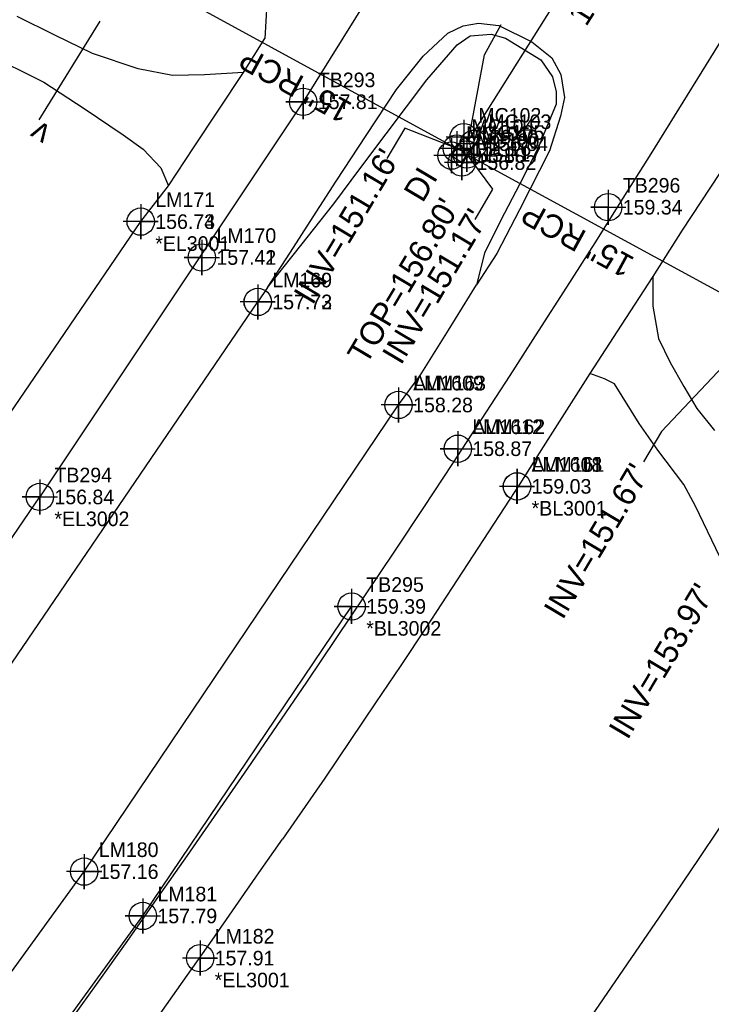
# Model space of a CAD drawing. Extents: x 2262665 to 2270527, y 505476 to 514960.
# Drawn here: x 2265771.7 to 2265890.1, y 508685.4 to 508854 of the extents above; entities that cross this region are included whole.
import ezdxf

# ---------------------------------------------------------------- set-up
doc = ezdxf.new("R2010")
doc.units = 0
for name, color, linetype in [('Exist Horizontal Alignment', 7, 'Continuous'), ('Exist Right of Way Control of Access Line', 7, 'Continuous'), ('Exist Roads EOP', 7, 'Continuous'), ('Exist Roads EOP Cogo Comment', 7, 'Continuous'), ('Exist Roads EOP Cogo Elevation', 7, 'Continuous'), ('Exist Roads EOP Cogo Number', 7, 'Continuous'), ('Exist Roads EOP Cogo Point CELL', 7, 'Continuous'), ('Exist Roads EOP Other', 7, 'Continuous'), ('Exist Roads EOT', 7, 'Continuous'), ('Exist Roads EOT Cogo Comment', 7, 'Continuous'), ('Exist Roads EOT Cogo Elevation', 7, 'Continuous'), ('Exist Roads EOT Cogo Number', 7, 'Continuous'), ('Exist Roads EOT Cogo Point CELL', 7, 'Continuous'), ('Exist Roads Soil', 7, 'Continuous'), ('Exist Structure Minor Culvert Topo', 7, 'Continuous'), ('Exist Structure Minor Culvert Topo Terminator', 7, 'Continuous'), ('Exist Structure Minor Drop Inlet', 7, 'Continuous'), ('Exist Structure Minor Drop Inlet Cogo Elevation', 7, 'Continuous'), ('Exist Structure Minor Drop Inlet Cogo Number', 7, 'Continuous'), ('Exist Structure Minor Drop Inlet Cogo Point CELL', 7, 'Continuous'), ('Exist Structure Minor Drop Inlet Text', 7, 'Continuous'), ('Exist Structure Minor Drop Inlet Top Elevation', 7, 'Continuous'), ('Exist Structure Minor Pipes RCP 15 Inch', 7, 'Continuous'), ('Exist Structure Minor Pipes RCP 15 Inch Cogo Elevation', 7, 'Continuous'), ('Exist Structure Minor Pipes RCP 15 Inch Cogo Number', 7, 'Continuous'), ('Exist Structure Minor Pipes RCP 15 Inch Cogo Point CELL', 7, 'Continuous'), ('Exist Structure Minor Pipes RCP 15 Inch Invert', 7, 'Continuous'), ('Exist Structure Minor Pipes RCP 15 Inch Leader', 7, 'Continuous'), ('Exist Structure Minor Pipes RCP 15 Inch Text', 7, 'Continuous')]:
    doc.layers.add(name, color=color, linetype=linetype)

msp = doc.modelspace()

# ---------------------------------------------------------------- linework, layer by layer
at = {"layer": 'Exist Horizontal Alignment'}
msp.add_arc((2263436.25, 510359.19), 2882, 309.60499, 355.6461, dxfattribs=at)
at = {"layer": 'Exist Right of Way Control of Access Line'}
for radius, end in [(2754.56, 355.6461), (2954.56, 339.73535)]:
    msp.add_arc((2263436.25, 510359.19), radius, 309.60499, end, dxfattribs=at)
at = {"layer": 'Exist Roads EOP'}
for points in [[(2265910.12, 508858.21), (2265905.83, 508851.47), (2265901.54, 508844.73), (2265897.25, 508838), (2265891.48, 508827.67), (2265885.09, 508817.97)], [(2265792.39, 508819.43), (2265797.17, 508825.59), (2265801.44, 508832.06), (2265805.72, 508838.52), (2265809.99, 508844.99), (2265813.65, 508850.79)], [(2265814.12, 508808.16), (2265819.79, 508815.33), (2265825.46, 508822.49), (2265829.92, 508828.48), (2265834.38, 508834.46), (2265841.35, 508843.7), (2265846.57, 508849.72), (2265848.81, 508851.24), (2265852.38, 508851.52), (2265854.86, 508850.83), (2265860.89, 508847.12), (2265862.9, 508844.22), (2265863.52, 508841.67), (2265863.48, 508839.57), (2265860.33, 508831.82), (2265857.2, 508825.77), (2265854.06, 508819.71), (2265851.22, 508814.06), (2265849.86, 508808.6)], [(2265756.07, 508766.2), (2265792.39, 508819.43)], [(2265885.09, 508817.97), (2265880.03, 508810.04), (2265874.65, 508801.73), (2265869.26, 508793.42), (2265865.26, 508787.14), (2265861.27, 508780.85), (2265857.27, 508774.56), (2265851.92, 508766.34), (2265846.57, 508758.12), (2265841.22, 508749.89), (2265836.89, 508743.46), (2265832.57, 508737.02), (2265828.24, 508730.59), (2265823.91, 508724.16), (2265816.65, 508713.72)], [(2265814.12, 508808.16), (2265812.43, 508805.68)], [(2265836.53, 508788.04), (2265840.23, 508793.07), (2265845.05, 508800.83), (2265849.86, 508808.6)], [(2264604.13, 507673.17), (2264652.18, 507710.12), (2264729.46, 507770.12), (2264804.34, 507827.5), (2264878.61, 507884.49), (2264953.4, 507941.83), (2265025.73, 507997.77), (2265100.61, 508055.34), (2265175.62, 508113.68), (2265249.21, 508173.29), (2265321.97, 508235.58), (2265396.59, 508304.14), (2265463.32, 508369.68), (2265525.52, 508435.63), (2265587.08, 508505.56), (2265646.09, 508576.73), (2265702.44, 508648.91), (2265758.48, 508726.47), (2265812.43, 508805.68)], [(2264622.96, 507650.09), (2264669.69, 507686.11), (2264747.6, 507746.03), (2264823.02, 507803.99), (2264895.49, 507859.73), (2264970.56, 507917.69), (2265042.91, 507973.75), (2265117.63, 508031.26), (2265192.77, 508089.56), (2265267.51, 508149.88), (2265340.79, 508212.44), (2265416.18, 508281.7), (2265483.07, 508347.24), (2265547.56, 508415.53), (2265609.81, 508485.51), (2265669.26, 508556.91), (2265726.09, 508630), (2265782.72, 508708.15), (2265836.53, 508788.04)], [(2265771.46, 508649.69), (2265775.99, 508656.02), (2265781.29, 508663.45), (2265786.58, 508670.88), (2265791.88, 508678.31), (2265796.12, 508684.35), (2265800.36, 508690.38), (2265804.6, 508696.42), (2265808.62, 508702.19), (2265812.63, 508707.96), (2265816.65, 508713.72)]]:
    msp.add_lwpolyline(points, dxfattribs=at)
at = {"layer": 'Exist Roads EOP Cogo Point CELL'}
for points in [[(2265792.39, 508822.43), (2265792.39, 508816.43), (2265792.39, 508819.43), (2265795.39, 508819.43), (2265789.39, 508819.43)], [(2265792.39, 508822.43), (2265792.39, 508816.43), (2265792.39, 508819.43), (2265795.39, 508819.43), (2265789.39, 508819.43)], [(2265812.42, 508808.68), (2265812.42, 508802.68), (2265812.42, 508805.68), (2265815.42, 508805.68), (2265809.42, 508805.68)], [(2265812.43, 508808.68), (2265812.43, 508802.68), (2265812.43, 508805.68), (2265815.43, 508805.68), (2265809.43, 508805.68)], [(2265836.53, 508791.04), (2265836.53, 508785.04), (2265836.53, 508788.04), (2265839.53, 508788.04), (2265833.53, 508788.04)], [(2265836.53, 508791.04), (2265836.53, 508785.04), (2265836.53, 508788.04), (2265839.53, 508788.04), (2265833.53, 508788.04)], [(2265856.8, 508777.11), (2265856.8, 508771.11), (2265856.8, 508774.11), (2265859.8, 508774.11), (2265853.8, 508774.11)], [(2265856.81, 508777.11), (2265856.81, 508771.11), (2265856.81, 508774.11), (2265859.81, 508774.11), (2265853.81, 508774.11)], [(2265856.81, 508777.11), (2265856.81, 508771.11), (2265856.81, 508774.11), (2265859.81, 508774.11), (2265853.81, 508774.11)], [(2265782.71, 508711.15), (2265782.71, 508705.15), (2265782.71, 508708.15), (2265785.71, 508708.15), (2265779.71, 508708.15)], [(2265782.72, 508711.15), (2265782.72, 508705.15), (2265782.72, 508708.15), (2265785.72, 508708.15), (2265779.72, 508708.15)], [(2265802.56, 508696.34), (2265802.56, 508690.34), (2265802.56, 508693.34), (2265805.56, 508693.34), (2265799.56, 508693.34)], [(2265802.56, 508696.34), (2265802.56, 508690.34), (2265802.56, 508693.34), (2265805.56, 508693.34), (2265799.56, 508693.34)]]:
    msp.add_lwpolyline(points, dxfattribs=at)
for centre in [(2265792.39, 508819.43), (2265792.39, 508819.43), (2265812.43, 508805.68), (2265812.42, 508805.68), (2265836.53, 508788.04), (2265836.53, 508788.04), (2265856.81, 508774.11), (2265856.81, 508774.11), (2265856.8, 508774.11), (2265782.71, 508708.15), (2265782.72, 508708.15), (2265802.56, 508693.34), (2265802.56, 508693.34)]:
    msp.add_circle(centre, 2.34, dxfattribs=at)
at = {"layer": 'Exist Roads EOP Other'}
msp.add_lwpolyline([(2265813.96, 508856.74), (2265813.65, 508850.79)], dxfattribs=at)
at = {"layer": 'Exist Roads EOT'}
for points in [[(2265966, 509095.96), (2265942.58, 509050.45), (2265904.19, 508979.11), (2265863.41, 508909.33), (2265820.21, 508839.95), (2265775.13, 508772.3)], [(2265814.12, 508808.16), (2265818.03, 508814.22), (2265821.94, 508820.28), (2265825.85, 508826.34), (2265831.01, 508834.18), (2265836.17, 508842.03), (2265840.75, 508847.78), (2265844.95, 508851.68), (2265847.58, 508852.94), (2265850.19, 508853.44), (2265853.69, 508853.02), (2265859.36, 508850.21), (2265862.75, 508847.46), (2265864.32, 508844.61), (2265864.91, 508840.71), (2265864.25, 508837.47), (2265862.39, 508831.53), (2265857.21, 508821.44), (2265853.34, 508814), (2265849.86, 508808.6)], [(2264355.6, 507490.59), (2264438.39, 507557.92), (2264515.74, 507619.63), (2264596.53, 507682.98), (2264644.8, 507719.95), (2264722.22, 507780.13), (2264797.31, 507837.32), (2264871.27, 507893.95), (2264945.98, 507951.46), (2265019.16, 508007.99), (2265093.77, 508065.17), (2265168.17, 508123.63), (2265241.66, 508182.89), (2265313.79, 508245.24), (2265388.67, 508313.15), (2265454.9, 508378.68), (2265516.64, 508444.01), (2265578.28, 508513.6), (2265637.19, 508584.7), (2265692.99, 508656.91), (2265748.78, 508733.7), (2265775.13, 508772.3)], [(2264387.25, 507447.54), (2264469.24, 507514.31), (2264548.37, 507577.38), (2264630.86, 507640.65), (2264676.76, 507676.3), (2264754.66, 507736.06), (2264830.22, 507794.41), (2264902.47, 507849.79), (2264977.44, 507907.47), (2265049.71, 507963.66), (2265125.01, 508021.39), (2265200.16, 508080.1), (2265274.69, 508140.15), (2265348.74, 508203.05), (2265424.49, 508272.43), (2265491.61, 508338.47), (2265557.1, 508407.36), (2265618.9, 508477.1), (2265678.7, 508548.94), (2265735.91, 508622.32), (2265792.76, 508700.56), (2265828.5, 508753.55)]]:
    msp.add_lwpolyline(points, dxfattribs=at)
at = {"layer": 'Exist Roads EOT Cogo Point CELL'}
for points in [[(2265820.21, 508842.95), (2265820.21, 508836.95), (2265820.21, 508839.95), (2265817.21, 508839.95), (2265823.21, 508839.95)], [(2265872.41, 508824.9), (2265872.41, 508818.9), (2265872.41, 508821.9), (2265869.41, 508821.9), (2265875.41, 508821.9)], [(2265802.86, 508816.3), (2265802.86, 508810.3), (2265802.86, 508813.3), (2265799.86, 508813.3), (2265805.86, 508813.3)], [(2265802.86, 508816.29), (2265802.86, 508810.29), (2265802.86, 508813.29), (2265799.86, 508813.29), (2265805.86, 508813.29)], [(2265846.66, 508783.56), (2265846.66, 508777.56), (2265846.66, 508780.56), (2265843.66, 508780.56), (2265849.66, 508780.56)], [(2265846.66, 508783.56), (2265846.66, 508777.56), (2265846.66, 508780.56), (2265843.66, 508780.56), (2265849.66, 508780.56)], [(2265775.13, 508775.3), (2265775.13, 508769.3), (2265775.13, 508772.3), (2265772.13, 508772.3), (2265778.13, 508772.3)], [(2265828.5, 508756.55), (2265828.5, 508750.55), (2265828.5, 508753.55), (2265825.5, 508753.55), (2265831.5, 508753.55)], [(2265792.75, 508703.56), (2265792.75, 508697.56), (2265792.75, 508700.56), (2265789.75, 508700.56), (2265795.75, 508700.56)], [(2265792.76, 508703.56), (2265792.76, 508697.56), (2265792.76, 508700.56), (2265789.76, 508700.56), (2265795.76, 508700.56)]]:
    msp.add_lwpolyline(points, dxfattribs=at)
for centre in [(2265820.21, 508839.95), (2265872.41, 508821.9), (2265802.86, 508813.29), (2265802.86, 508813.3), (2265846.66, 508780.56), (2265846.66, 508780.56), (2265775.13, 508772.3), (2265828.5, 508753.55), (2265792.75, 508700.56), (2265792.76, 508700.56)]:
    msp.add_circle(centre, 2.34, dxfattribs=at)
at = {"layer": 'Exist Roads Soil'}
for points in [[(2265749.14, 508856.82), (2265755.11, 508853.6), (2265765.64, 508848.34), (2265775.81, 508843.33), (2265782.69, 508838.81), (2265789.38, 508834.27), (2265792.84, 508831.82), (2265795.84, 508828.66), (2265797.17, 508825.59)], [(2265809.99, 508844.99), (2265803.32, 508844.59), (2265797.85, 508844.44), (2265791.95, 508845.58), (2265784.15, 508848.21), (2265777.68, 508851.37), (2265771.22, 508854.53)], [(2265880.03, 508810.04), (2265880.04, 508804.96), (2265881.01, 508799.43), (2265883.04, 508795.33), (2265885.37, 508791.19), (2265887.56, 508787.45), (2265890.6, 508783.65)], [(2265891.5, 508762.02), (2265887.34, 508770.72), (2265885.38, 508774.44), (2265880.91, 508780.32), (2265877.69, 508784.89), (2265873.5, 508791.64), (2265871.79, 508792.54), (2265869.26, 508793.42)]]:
    msp.add_lwpolyline(points, dxfattribs=at)
at = {"layer": 'Exist Structure Minor Culvert Topo'}
msp.add_line((2265775.02, 508836.84), (2265785.47, 508853.73), dxfattribs=at)
at = {"layer": 'Exist Structure Minor Drop Inlet'}
msp.add_lwpolyline([(2265847.68, 508833.88), (2265845.58, 508830.74), (2265847.37, 508829.55), (2265849.47, 508832.69)], close=True, dxfattribs=at)
at = {"layer": 'Exist Structure Minor Drop Inlet Cogo Point CELL'}
for points in [[(2265847.68, 508836.88), (2265847.68, 508830.88), (2265847.68, 508833.88), (2265850.68, 508833.88), (2265844.68, 508833.88)], [(2265849.39, 508835.78), (2265849.39, 508829.78), (2265849.39, 508832.78), (2265852.39, 508832.78), (2265846.39, 508832.78)], [(2265845.58, 508833.73), (2265845.58, 508827.73), (2265845.58, 508830.73), (2265848.58, 508830.73), (2265842.58, 508830.73)], [(2265847.37, 508832.55), (2265847.37, 508826.55), (2265847.37, 508829.55), (2265850.37, 508829.55), (2265844.37, 508829.55)]]:
    msp.add_lwpolyline(points, dxfattribs=at)
for centre in [(2265847.68, 508833.88), (2265849.39, 508832.78), (2265845.58, 508830.73), (2265847.37, 508829.55)]:
    msp.add_circle(centre, 2.34, dxfattribs=at)
at = {"layer": 'Exist Structure Minor Pipes RCP 15 Inch'}
for p, q in [((2265848.52, 508833.34), (2265883.53, 508889.1)), ((2265793.86, 508860.74), (2265846.5, 508831.94)), ((2265848.19, 508830.94), (2265899.79, 508802.84))]:
    msp.add_line(p, q, dxfattribs=at)
at = {"layer": 'Exist Structure Minor Pipes RCP 15 Inch Cogo Point CELL'}
for points in [[(2265846.5, 508834.94), (2265846.5, 508828.94), (2265846.5, 508831.94), (2265849.5, 508831.94), (2265843.5, 508831.94)], [(2265848.19, 508833.94), (2265848.19, 508827.94), (2265848.19, 508830.94), (2265851.19, 508830.94), (2265845.19, 508830.94)]]:
    msp.add_lwpolyline(points, dxfattribs=at)
for centre in [(2265846.5, 508831.94), (2265848.19, 508830.94)]:
    msp.add_circle(centre, 2.34, dxfattribs=at)
at = {"layer": 'Exist Structure Minor Pipes RCP 15 Inch Leader'}
for points in [[(2265848.52, 508833.34), (2265851.22, 508847.99), (2265854.07, 508853.16)], [(2265846.5, 508831.94), (2265837.58, 508835.41), (2265834.51, 508830.25)], [(2265848.19, 508830.94), (2265852.63, 508824.97), (2265849.56, 508819.82)], [(2265899.79, 508802.84), (2265881.54, 508783.48), (2265878.48, 508778.32)]]:
    msp.add_lwpolyline(points, dxfattribs=at)

# ---------------------------------------------------------------- texts
at = {"layer": 'Exist Roads EOP Cogo Comment'}
for s, p in [('*EL3001', (2265794.89, 508814.43)), ('*EL3001', (2265794.89, 508814.43)), ('*BL3001', (2265859.3, 508769.11)), ('*BL3001', (2265859.31, 508769.11)), ('*BL3001', (2265859.31, 508769.11)), ('*EL3001', (2265805.06, 508688.34)), ('*EL3001', (2265805.06, 508688.34))]:
    msp.add_text(s, height=2.5, dxfattribs=at).set_placement(p)
at = {"layer": 'Exist Roads EOP Cogo Elevation'}
for s, p in [('156.74', (2265794.89, 508818.18)), ('156.73', (2265794.89, 508818.18)), ('157.73', (2265814.92, 508804.43)), ('157.72', (2265814.93, 508804.43)), ('158.28', (2265839.03, 508786.79)), ('158.28', (2265839.03, 508786.79)), ('159.03', (2265859.3, 508772.86)), ('159.03', (2265859.31, 508772.86)), ('159.03', (2265859.31, 508772.86)), ('157.16', (2265785.21, 508706.9)), ('157.16', (2265785.22, 508706.9)), ('157.91', (2265805.06, 508692.09)), ('157.91', (2265805.06, 508692.09))]:
    msp.add_text(s, height=2.5, dxfattribs=at).set_placement(p)
at = {"layer": 'Exist Roads EOP Cogo Number'}
for s, p in [('LM171', (2265794.89, 508821.93)), ('LM171', (2265794.89, 508821.93)), ('LM169', (2265814.92, 508808.18)), ('LM169', (2265814.93, 508808.18)), ('ALM163', (2265839.03, 508790.54)), ('LM1609', (2265839.03, 508790.54)), ('ALM161', (2265859.3, 508776.61)), ('LM1608', (2265859.31, 508776.61)), ('LM1611', (2265859.31, 508776.61)), ('LM180', (2265785.21, 508710.65)), ('LM180', (2265785.22, 508710.65)), ('LM182', (2265805.06, 508695.84)), ('LM182', (2265805.06, 508695.84))]:
    msp.add_text(s, height=2.5, dxfattribs=at).set_placement(p)
at = {"layer": 'Exist Roads EOT Cogo Comment'}
for s, p in [('*EL3002', (2265777.63, 508767.3)), ('*BL3002', (2265831, 508748.55))]:
    msp.add_text(s, height=2.5, dxfattribs=at).set_placement(p)
at = {"layer": 'Exist Roads EOT Cogo Elevation'}
for s, p in [('157.81', (2265822.71, 508838.7)), ('159.34', (2265874.91, 508820.65)), ('157.42', (2265805.36, 508812.04)), ('157.41', (2265805.36, 508812.05)), ('158.87', (2265849.16, 508779.31)), ('158.87', (2265849.16, 508779.31)), ('156.84', (2265777.63, 508771.05)), ('159.39', (2265831, 508752.3)), ('157.79', (2265795.25, 508699.31)), ('157.79', (2265795.26, 508699.31))]:
    msp.add_text(s, height=2.5, dxfattribs=at).set_placement(p)
at = {"layer": 'Exist Roads EOT Cogo Number'}
for s, p in [('TB293', (2265822.71, 508842.45)), ('TB296', (2265874.91, 508824.4)), ('LM170', (2265805.36, 508815.79)), ('LM170', (2265805.36, 508815.8)), ('ALM162', (2265849.16, 508783.06)), ('LM1612', (2265849.16, 508783.06)), ('TB294', (2265777.63, 508774.8)), ('TB295', (2265831, 508756.05)), ('LM181', (2265795.25, 508703.06)), ('LM181', (2265795.26, 508703.06))]:
    msp.add_text(s, height=2.5, dxfattribs=at).set_placement(p)
at = {"layer": 'Exist Structure Minor Culvert Topo Terminator'}
msp.add_text('v', height=4, rotation=148.2655, dxfattribs=at).set_placement((2265777.27, 508835.45))
at = {"layer": 'Exist Structure Minor Drop Inlet Cogo Elevation'}
for s, p in [('156.80', (2265850.18, 508832.63)), ('156.84', (2265851.89, 508831.53)), ('156.80', (2265848.08, 508829.48)), ('156.82', (2265849.87, 508828.3))]:
    msp.add_text(s, height=2.5, dxfattribs=at).set_placement(p)
at = {"layer": 'Exist Structure Minor Drop Inlet Cogo Number'}
for s, p in [('MC102', (2265850.18, 508836.38)), ('MC103', (2265851.89, 508835.28)), ('MC101', (2265848.08, 508833.23)), ('MC100', (2265849.87, 508832.05))]:
    msp.add_text(s, height=2.5, dxfattribs=at).set_placement(p)
at = {"layer": 'Exist Structure Minor Drop Inlet Text'}
msp.add_text('DI', height=4, rotation=59.2519, dxfattribs=at).set_placement((2265840.65, 508822.51))
at = {"layer": 'Exist Structure Minor Drop Inlet Top Elevation'}
msp.add_text("TOP=156.80'", height=4, rotation=59.2519, dxfattribs=at).set_placement((2265831.01, 508794.76))
at = {"layer": 'Exist Structure Minor Pipes RCP 15 Inch Cogo Elevation'}
for s, p in [('151.16', (2265849, 508830.69)), ('151.17', (2265850.69, 508829.69))]:
    msp.add_text(s, height=2.5, dxfattribs=at).set_placement(p)
at = {"layer": 'Exist Structure Minor Pipes RCP 15 Inch Cogo Number'}
for s, p in [('MC104', (2265849, 508834.44)), ('MC105', (2265850.69, 508833.44))]:
    msp.add_text(s, height=2.5, dxfattribs=at).set_placement(p)
at = {"layer": 'Exist Structure Minor Pipes RCP 15 Inch Invert'}
for s, p in [("INV=151.16'", (2265821.81, 508804.99)), ("INV=151.17'", (2265836.95, 508794.72)), ("INV=151.67'", (2265864.62, 508751.11)), ("INV=153.97'", (2265875.73, 508730.56))]:
    msp.add_text(s, height=4, rotation=59.2519, dxfattribs=at).set_placement(p)
at = {"layer": 'Exist Structure Minor Pipes RCP 15 Inch Text'}
for rotation, p in [(57.874, (2265868.64, 508852.69)), (151.3216, (2265828.82, 508839.59)), (151.4237, (2265877.13, 508813.14))]:
    msp.add_text('15" RCP', height=4, rotation=rotation, dxfattribs=at).set_placement(p)

doc.saveas('drawing.dxf')
